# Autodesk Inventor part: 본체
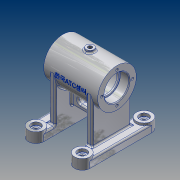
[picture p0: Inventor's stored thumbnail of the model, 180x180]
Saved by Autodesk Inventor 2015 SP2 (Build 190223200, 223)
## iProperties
Created: 2015-11
Part Number: 본체
Material: 알루미늄 6061
Document SubType Name: Modeling
Designer: AMC
Density: 2.7 g/cm^3
Appearance: 알루미늄 - 평지
Mass: 371.735 g
Surface Area: 456.261 cm^2
Volume: 137.68 cm^3
Author: AMC
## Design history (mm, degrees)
sketch "스케치1"
  geometry: C1 r 25 at (0, 0); 1 further point
  constraints: 1 centre point, 1 coincident
  dimensions: "d0" = 50 diameter of C1
extrude "돌출1" new body sketch "스케치1" stored distance "d1" = 70; taper "d2" = 0 deg
node "작업 평면2"
sketch "스케치2" dims "d14" = 20, "d17" = 20
  geometry: L1 (-40, -40)-(40, -40); L2 (40, -40)-(40, 40); L3 (40, 40)-(-40, 40); L4 (-40, 40)-(-40, -40); L5 (-40, -40)-(40, 40); L6 (40, -40)-(-40, 40); L7 (-20, 40)-(20, 40); L8 (20, 40)-(20, -40); L9 (20, -40)-(-20, -40); L10 (-20, -40)-(-20, 40); C1 r 10 at (30, 40); C2 r 10 at (-30, -40); 3 further points
  constraints: 20 end point, 6 point on line, 4 parallel, 2 centre point, 2 horizontal, 2 horizontal alignment, 2 midpoint, 2 perpendicular, 4 other
  dimensions: "d4" = 80 distance of L3.end L2.end; "d5" = 80 distance of L2.end L1.end; "d15" = 20 diameter of C1; "d16" = 20 diameter of C2; "d18" = 10 distance from line of L4 point (-30, 40); "d19" = 10 distance from line of L2 C1.centre; "d20" = 10 distance from line of point (30, -40) L2; "d21" = 10 distance from line of L4 C2.centre
extrude "돌출2" join sketch "스케치2" distance "d22" = 10; taper "d23" = 0 deg
extrude "돌출3" join sketch "스케치2" distance "d24" = 13; taper "d25" = 0 deg
sketch "스케치6"
  geometry: L1 (20, -68)-(20, -58) reference; L2 (40, -68)-(20, -68) reference; L3 (40, -68)-(40, -58) reference; L4 (20, -58)-(40, -58) reference; L5 (40, -55)-(20, -55) reference; L6 (-40, -68)-(-40, -58) reference; L7 (-20, -68)-(-40, -68) reference; L8 (-20, -68)-(-20, -58) reference; L9 (-40, -58)-(-20, -58) reference; L10 (-20, -55)-(-40, -55) reference; L11 (20, -68)-(28, -68); L12 (28, -68)-(28, 0); L13 (28, 0)-(20, 0); L14 (20, 0)-(20, -68); L15 (-20, -68)-(-28, -68); L16 (-28, -68)-(-28, 0); L17 (-28, 0)-(-20, 0); L18 (-20, 0)-(-20, -68); L19 (35, -25)-(35, 25) reference; L20 (-35, 25)-(-35, -25) reference; L21 (-20, -25)-(-20, -45); L22 (-20, -45)-(20, -45); L23 (20, -45)-(20, -25); L24 (20, -35)-(-20, -35); L25 (8, -35)-(-8, -35); L26 (8, -31.5)-(-8, -31.5); L27 (-8, -38.5)-(8, -38.5); L28 (20, -19)-(-20, -19); L29 (0, -19)-(0, -45); A1 r 3.5 centre (8, -35) between (8, -38.5) and (8, -31.5); A2 r 3.5 centre (-8, -35) between (-8, -31.5) and (-8, -38.5); 3 further points
  constraints: 36 end point, 6 midpoint, 6 parallel, 6 point on line, 4 point on circle, 4 tangent, 3 perpendicular, 2 centre point, 2 horizontal, 1 coincident
  dimensions: "d26" = 8 distance between parallel lines of L12 L14; "d27" = 8 distance between parallel lines of L16 L18; "d28" = 68 distance between parallel lines of L2 L13; "d29" = 68 distance between parallel lines of L15 L17; "d32" = 7 diameter of A2; "d33" = 33 distance between parallel lines of L7 L25; "d39" = 26 distance between parallel lines of L22 L28; "d40" = 10 distance between parallel lines of L22 L24; "d108" = 23 dimension on A2 A1
  node "투영된 루프1"
  node "투영된 루프2"
  node "투영된 루프3"
extrude "돌출4" join sketch "스케치6" stored distance "d34" = 50; taper "d35" = 0 deg
extrude "돌출5" join sketch "스케치6" stored distance "d36" = 8; taper "d37" = 0 deg
hole "구멍1" diameter "d43" = 6; stored, may be unused: countersink angle "d47" = 90 deg, drill point angle "d49" = 118 deg; dims "d41" = 10, "d42" = 10, "d44" = 6, "d45" = 12, "d46" = 4, "d48" = 8
fillet "모깎기1" dims "d50" = 0.3
fillet "모깎기2" dims "d51" = 0.3
chamfer "모따기1" distance "d52" = 1; stored, may be unused: second distance "d53" = 2, angle "d54" = 45 deg
sketch "스케치7"
  geometry: C1 r 5 at (0, 0); 1 further point
  constraints: 1 centre point, 1 coincident
  dimensions: "d100" = 10 diameter of C1
extrude "돌출6" join sketch "스케치7" distance "d101" = 28; taper "d102" = 0 deg
hole "구멍2" diameter "d57" = 32; stored, may be unused: countersink angle "d61" = 90 deg, drill point angle "d63" = 0 deg; dims "d55" = 10, "d56" = 10, "d58" = 6, "d59" = 12, "d60" = 4, "d62" = 12
hole "구멍3" diameter "d66" = 28; stored, may be unused: countersink angle "d70" = 90 deg, drill point angle "d72" = 0 deg; dims "d64" = 10, "d65" = 10, "d67" = 6, "d68" = 12, "d69" = 4, "d71" = 2
hole "구멍5" diameter "d84" = 32; stored, may be unused: countersink angle "d88" = 90 deg, drill point angle "d90" = 0 deg; dims "d82" = 10, "d83" = 10, "d85" = 6, "d86" = 12, "d87" = 4, "d89" = 12
sketch "스케치8"
  geometry: L1 (0, 0)-(12.5, -21.651); L2 (0, 0)-(25, 0); C1 r 16 at (0, 0) reference; A1 r 25 centre (0, 0) between (12.5, -21.651) and (25, 0) reference; 2 further points
  constraints: 4 end point, 2 point on circle, 1 coincident, 1 horizontal
  dimensions: "d103" = 60 deg angle of L1 L2
  node "투영된 루프4"
node "작업 평면6"
  node "작업 평면5"
sketch "스케치9"
  geometry: C1 r 6 at (0, 0); 1 further point
  constraints: 1 centre point, 1 coincident
  dimensions: "d105" = 12 diameter of C1
extrude "돌출7" join sketch "스케치9" distance "d106" = 28; taper "d107" = 0 deg
hole "구멍4" diameter "d75" = 40; stored, may be unused: countersink angle "d79" = 90 deg, drill point angle "d81" = 0 deg; dims "d73" = 10, "d74" = 10, "d76" = 6, "d77" = 12, "d78" = 4, "d80" = 42
hole "구멍6" diameter "d93" = 28; stored, may be unused: countersink angle "d97" = 90 deg, drill point angle "d99" = 0 deg; dims "d91" = 10, "d92" = 10, "d94" = 6, "d95" = 12, "d96" = 4, "d98" = 2
fillet "모깎기3" dims "d109" = 2
fillet "모깎기4" dims "d110" = 2
fillet "모깎기5" dims "d111" = 2
fillet "모깎기6" dims "d112" = 2
fillet "모깎기7" dims "d113" = 2
hole "구멍7" diameter "d116" = 5.188; stored, may be unused: countersink angle "d120" = 90 deg, drill point angle "d122" = 0 deg; dims "d114" = 10, "d115" = 10, "d117" = 12, "d118" = 12, "d119" = 4, "d121" = 16
hole "구멍8" diameter "d125" = 5.188; stored, may be unused: countersink angle "d129" = 90 deg, drill point angle "d131" = 0 deg; dims "d123" = 10, "d124" = 10, "d126" = 12, "d127" = 12, "d128" = 4, "d130" = 16
sketch "스케치10" dims "d132" = 40
  geometry: C1 r 16 at (0, 0) reference; C2 r 25 at (0, 0) reference; 3 further points
  constraints: 2 vertical alignment, 1 coincident, 2 other
hole "구멍9" sketch "스케치10" at (0, 20) diameter "d133" = 3.242; stored, may be unused: countersink angle "d137" = 90 deg, drill point angle "d139" = 118 deg; dims "d134" = 8, "d135" = 12, "d136" = 4, "d138" = 10
node "작업 평면7"
sketch "스케치12"
  geometry: L1 (-22.5, 3.5)-(22.5, 3.5); L2 (22.5, 3.5)-(22.5, -3.5); L3 (22.5, -3.5)-(-22.5, -3.5); L4 (-22.5, -3.5)-(-22.5, 3.5); L5 (-22.5, 0)-(22.5, 0); L6 (0, 3.5)-(0, -3.5); L7 (-35, 25)-(-35, -25) reference; 3 further points
  constraints: 6 midpoint, 4 end point, 1 coincident, 1 horizontal, 2 other
  dimensions: "d144" = 45 distance between parallel lines of L2 L4; "d145" = 7 distance between parallel lines of L3 L1; "d146" = 0 distance of point (0, 0) point (0, 0); "d148" = 35 distance between parallel lines of L6 L7
feature "엠보싱1" sketch "스케치12" dims "d22" = 10, "d149" = 0.5, "d150" = 0
fillet "모깎기8" dims "d151" = 3
fillet "모깎기9" dims "d152" = 0.3
chamfer "모따기2" distance "d153" = 1; stored, may be unused: second distance "d154" = 2, angle "d155" = 45 deg
node "솔리드1"
mirror "대칭1"
mirror "대칭2"
pattern_circular "원형 패턴1" dims angle "d141" = 360 deg
mirror "대칭3"
node "작업 평면3"
node "작업 평면4"
node "투영된 루프5"
other parameters: "d3" = -68, "d104" = -25, "d143" = 0
